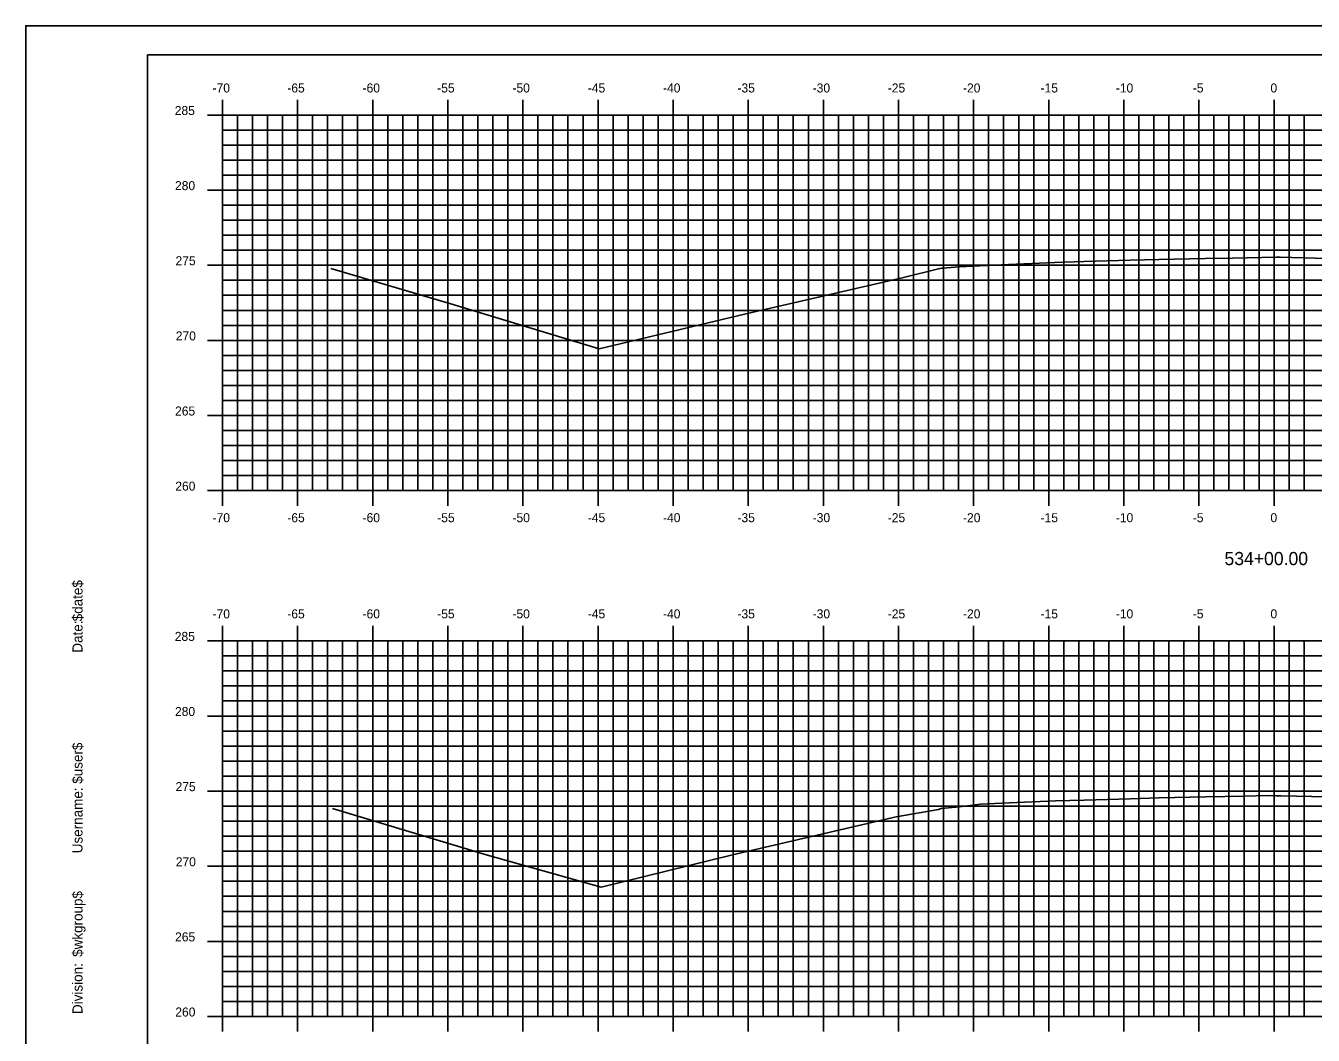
# Model space of a CAD drawing. Extents: x 1168600 to 1177589, y 610178 to 611246.
# Drawn here: x 1176974.3 to 1177060, y 610311.6 to 610378.7 of the extents above; entities that cross this region are included whole.
import ezdxf

# ---------------------------------------------------------------- set-up
doc = ezdxf.new("R2010")
doc.units = 0
for name, color, linetype in [('_Construction', 7, 'Continuous'), ('_Station Equation', 7, 'Continuous'), ('H_V ANNOTATION', 7, 'Continuous'), ('MAJOR', 7, 'Continuous'), ('MINOR', 7, 'Continuous')]:
    doc.layers.add(name, color=color, linetype=linetype)

msp = doc.modelspace()

# ---------------------------------------------------------------- linework, layer by layer
at = {"layer": '_Construction'}
for p, q in [((1177142.411, 610376.801), (1176982.411, 610376.801)), ((1176982.411, 610376.801), (1176982.411, 610271.801))]:
    msp.add_line(p, q, dxfattribs=at)
msp.add_lwpolyline([(1176974.318, 610268.742), (1177144.318, 610268.742), (1177144.318, 610378.742), (1176974.318, 610378.742)], close=True, dxfattribs=at)
at = {"layer": '_Station Equation'}
for points in [[(1176994.615, 610362.588), (1177002.605, 610360.242), (1177012.495, 610357.244), (1177022.164, 610359.54), (1177032.652, 610361.968), (1177035.16, 610362.578), (1177035.167, 610362.579), (1177035.338, 610362.615), (1177036.481, 610362.688), (1177037.824, 610362.767), (1177039.741, 610362.851), (1177042.824, 610362.985), (1177044.74, 610363.042), (1177047.824, 610363.13), (1177049.739, 610363.175), (1177052.824, 610363.249), (1177054.635, 610363.282), (1177057.569, 610363.335), (1177057.67, 610363.334), (1177057.824, 610363.333), (1177060.917, 610363.258)], [(1176994.739, 610326.65), (1177004.903, 610323.576), (1177012.616, 610321.408), (1177021.362, 610323.562), (1177032.259, 610326.084), (1177035.076, 610326.571), (1177035.254, 610326.649), (1177036.481, 610326.762), (1177037.863, 610326.942), (1177039.773, 610327.021), (1177042.863, 610327.151), (1177044.772, 610327.208), (1177047.863, 610327.299), (1177049.771, 610327.347), (1177052.863, 610327.424), (1177055.432, 610327.474), (1177057.021, 610327.504), (1177057.547, 610327.496), (1177057.863, 610327.493), (1177060.963, 610327.422)]]:
    msp.add_lwpolyline(points, dxfattribs=at)
at = {"layer": 'MAJOR'}
for p, q in [((1176987.411, 610373.803), (1176987.411, 610372.801)), ((1176992.411, 610373.803), (1176992.411, 610372.801)), ((1176997.411, 610373.803), (1176997.411, 610372.801)), ((1177002.411, 610373.803), (1177002.411, 610372.801)), ((1177007.411, 610373.803), (1177007.411, 610372.801)), ((1177012.411, 610373.803), (1177012.411, 610372.801)), ((1177017.411, 610373.803), (1177017.411, 610372.801)), ((1177022.411, 610373.803), (1177022.411, 610372.801)), ((1177027.411, 610373.803), (1177027.411, 610372.801)), ((1177032.411, 610373.803), (1177032.411, 610372.801)), ((1177037.411, 610373.803), (1177037.411, 610372.801)), ((1177042.411, 610373.803), (1177042.411, 610372.801)), ((1177047.411, 610373.803), (1177047.411, 610372.801)), ((1177052.411, 610373.803), (1177052.411, 610372.801)), ((1177057.411, 610373.803), (1177057.411, 610372.801)), ((1176986.409, 610372.801), (1176987.411, 610372.801)), ((1176987.411, 610372.801), (1177127.411, 610372.801)), ((1176987.411, 610347.801), (1176987.411, 610372.801)), ((1176987.411, 610347.801), (1176987.411, 610372.801)), ((1176987.411, 610372.801), (1177127.411, 610372.801)), ((1176992.411, 610347.801), (1176992.411, 610372.801)), ((1176997.411, 610347.801), (1176997.411, 610372.801)), ((1177002.411, 610347.801), (1177002.411, 610372.801)), ((1177007.411, 610347.801), (1177007.411, 610372.801)), ((1177012.411, 610347.801), (1177012.411, 610372.801)), ((1177017.411, 610347.801), (1177017.411, 610372.801)), ((1177022.411, 610347.801), (1177022.411, 610372.801)), ((1177027.411, 610347.801), (1177027.411, 610372.801)), ((1177032.411, 610347.801), (1177032.411, 610372.801)), ((1177037.411, 610347.801), (1177037.411, 610372.801)), ((1177042.411, 610347.801), (1177042.411, 610372.801)), ((1177047.411, 610347.801), (1177047.411, 610372.801)), ((1177052.411, 610347.801), (1177052.411, 610372.801)), ((1177057.411, 610347.801), (1177057.411, 610372.801)), ((1176986.409, 610367.801), (1176987.411, 610367.801)), ((1176987.411, 610367.801), (1177127.411, 610367.801)), ((1176986.409, 610362.801), (1176987.411, 610362.801)), ((1176987.411, 610362.801), (1177127.411, 610362.801)), ((1176986.409, 610357.801), (1176987.411, 610357.801)), ((1176987.411, 610357.801), (1177127.411, 610357.801)), ((1176986.409, 610352.801), (1176987.411, 610352.801)), ((1176987.411, 610352.801), (1177127.411, 610352.801)), ((1176986.409, 610347.801), (1176987.411, 610347.801)), ((1176987.411, 610347.801), (1177127.411, 610347.801)), ((1176987.411, 610347.801), (1177127.411, 610347.801)), ((1176987.411, 610346.799), (1176987.411, 610347.801)), ((1176992.411, 610346.799), (1176992.411, 610347.801)), ((1176997.411, 610346.799), (1176997.411, 610347.801)), ((1177002.411, 610346.799), (1177002.411, 610347.801)), ((1177007.411, 610346.799), (1177007.411, 610347.801)), ((1177012.411, 610346.799), (1177012.411, 610347.801)), ((1177017.411, 610346.799), (1177017.411, 610347.801)), ((1177022.411, 610346.799), (1177022.411, 610347.801)), ((1177027.411, 610346.799), (1177027.411, 610347.801)), ((1177032.411, 610346.799), (1177032.411, 610347.801)), ((1177037.411, 610346.799), (1177037.411, 610347.801)), ((1177042.411, 610346.799), (1177042.411, 610347.801)), ((1177047.411, 610346.799), (1177047.411, 610347.801)), ((1177052.411, 610346.799), (1177052.411, 610347.801)), ((1177057.411, 610346.799), (1177057.411, 610347.801)), ((1176987.411, 610338.803), (1176987.411, 610337.801)), ((1176992.411, 610338.803), (1176992.411, 610337.801)), ((1176997.411, 610338.803), (1176997.411, 610337.801)), ((1177002.411, 610338.803), (1177002.411, 610337.801)), ((1177007.411, 610338.803), (1177007.411, 610337.801)), ((1177012.411, 610338.803), (1177012.411, 610337.801)), ((1177017.411, 610338.803), (1177017.411, 610337.801)), ((1177022.411, 610338.803), (1177022.411, 610337.801)), ((1177027.411, 610338.803), (1177027.411, 610337.801)), ((1177032.411, 610338.803), (1177032.411, 610337.801)), ((1177037.411, 610338.803), (1177037.411, 610337.801)), ((1177042.411, 610338.803), (1177042.411, 610337.801)), ((1177047.411, 610338.803), (1177047.411, 610337.801)), ((1177052.411, 610338.803), (1177052.411, 610337.801)), ((1177057.411, 610338.803), (1177057.411, 610337.801)), ((1176986.409, 610337.801), (1176987.411, 610337.801)), ((1176987.411, 610337.801), (1177127.411, 610337.801)), ((1176987.411, 610312.801), (1176987.411, 610337.801)), ((1176987.411, 610312.801), (1176987.411, 610337.801)), ((1176987.411, 610337.801), (1177127.411, 610337.801)), ((1176992.411, 610312.801), (1176992.411, 610337.801)), ((1176997.411, 610312.801), (1176997.411, 610337.801)), ((1177002.411, 610312.801), (1177002.411, 610337.801)), ((1177007.411, 610312.801), (1177007.411, 610337.801)), ((1177012.411, 610312.801), (1177012.411, 610337.801)), ((1177017.411, 610312.801), (1177017.411, 610337.801)), ((1177022.411, 610312.801), (1177022.411, 610337.801)), ((1177027.411, 610312.801), (1177027.411, 610337.801)), ((1177032.411, 610312.801), (1177032.411, 610337.801)), ((1177037.411, 610312.801), (1177037.411, 610337.801)), ((1177042.411, 610312.801), (1177042.411, 610337.801)), ((1177047.411, 610312.801), (1177047.411, 610337.801)), ((1177052.411, 610312.801), (1177052.411, 610337.801)), ((1177057.411, 610312.801), (1177057.411, 610337.801)), ((1176986.409, 610332.801), (1176987.411, 610332.801)), ((1176987.411, 610332.801), (1177127.411, 610332.801)), ((1176986.409, 610327.801), (1176987.411, 610327.801)), ((1176987.411, 610327.801), (1177127.411, 610327.801)), ((1176986.409, 610322.801), (1176987.411, 610322.801)), ((1176987.411, 610322.801), (1177127.411, 610322.801)), ((1176986.409, 610317.801), (1176987.411, 610317.801)), ((1176987.411, 610317.801), (1177127.411, 610317.801)), ((1176986.409, 610312.801), (1176987.411, 610312.801)), ((1176987.411, 610312.801), (1177127.411, 610312.801)), ((1176987.411, 610312.801), (1177127.411, 610312.801)), ((1176987.411, 610311.799), (1176987.411, 610312.801)), ((1176992.411, 610311.799), (1176992.411, 610312.801)), ((1176997.411, 610311.799), (1176997.411, 610312.801)), ((1177002.411, 610311.799), (1177002.411, 610312.801)), ((1177007.411, 610311.799), (1177007.411, 610312.801)), ((1177012.411, 610311.799), (1177012.411, 610312.801)), ((1177017.411, 610311.799), (1177017.411, 610312.801)), ((1177022.411, 610311.799), (1177022.411, 610312.801)), ((1177027.411, 610311.799), (1177027.411, 610312.801)), ((1177032.411, 610311.799), (1177032.411, 610312.801)), ((1177037.411, 610311.799), (1177037.411, 610312.801)), ((1177042.411, 610311.799), (1177042.411, 610312.801)), ((1177047.411, 610311.799), (1177047.411, 610312.801)), ((1177052.411, 610311.799), (1177052.411, 610312.801)), ((1177057.411, 610311.799), (1177057.411, 610312.801))]:
    msp.add_line(p, q, dxfattribs=at)
at = {"layer": 'MINOR'}
for p, q in [((1176988.411, 610347.801), (1176988.411, 610372.801)), ((1176989.411, 610347.801), (1176989.411, 610372.801)), ((1176990.411, 610347.801), (1176990.411, 610372.801)), ((1176991.411, 610347.801), (1176991.411, 610372.801)), ((1176993.411, 610347.801), (1176993.411, 610372.801)), ((1176994.411, 610347.801), (1176994.411, 610372.801)), ((1176995.411, 610347.801), (1176995.411, 610372.801)), ((1176996.411, 610347.801), (1176996.411, 610372.801)), ((1176998.411, 610347.801), (1176998.411, 610372.801)), ((1176999.411, 610347.801), (1176999.411, 610372.801)), ((1177000.411, 610347.801), (1177000.411, 610372.801)), ((1177001.411, 610347.801), (1177001.411, 610372.801)), ((1177003.411, 610347.801), (1177003.411, 610372.801)), ((1177004.411, 610347.801), (1177004.411, 610372.801)), ((1177005.411, 610347.801), (1177005.411, 610372.801)), ((1177006.411, 610347.801), (1177006.411, 610372.801)), ((1177008.411, 610347.801), (1177008.411, 610372.801)), ((1177009.411, 610347.801), (1177009.411, 610372.801)), ((1177010.411, 610347.801), (1177010.411, 610372.801)), ((1177011.411, 610347.801), (1177011.411, 610372.801)), ((1177013.411, 610347.801), (1177013.411, 610372.801)), ((1177014.411, 610347.801), (1177014.411, 610372.801)), ((1177015.411, 610347.801), (1177015.411, 610372.801)), ((1177016.411, 610347.801), (1177016.411, 610372.801)), ((1177018.411, 610347.801), (1177018.411, 610372.801)), ((1177019.411, 610347.801), (1177019.411, 610372.801)), ((1177020.411, 610347.801), (1177020.411, 610372.801)), ((1177021.411, 610347.801), (1177021.411, 610372.801)), ((1177023.411, 610347.801), (1177023.411, 610372.801)), ((1177024.411, 610347.801), (1177024.411, 610372.801)), ((1177025.411, 610347.801), (1177025.411, 610372.801)), ((1177026.411, 610347.801), (1177026.411, 610372.801)), ((1177028.411, 610347.801), (1177028.411, 610372.801)), ((1177029.411, 610347.801), (1177029.411, 610372.801)), ((1177030.411, 610347.801), (1177030.411, 610372.801)), ((1177031.411, 610347.801), (1177031.411, 610372.801)), ((1177033.411, 610347.801), (1177033.411, 610372.801)), ((1177034.411, 610347.801), (1177034.411, 610372.801)), ((1177035.411, 610347.801), (1177035.411, 610372.801)), ((1177036.411, 610347.801), (1177036.411, 610372.801)), ((1177038.411, 610347.801), (1177038.411, 610372.801)), ((1177039.411, 610347.801), (1177039.411, 610372.801)), ((1177040.411, 610347.801), (1177040.411, 610372.801)), ((1177041.411, 610347.801), (1177041.411, 610372.801)), ((1177043.411, 610347.801), (1177043.411, 610372.801)), ((1177044.411, 610347.801), (1177044.411, 610372.801)), ((1177045.411, 610347.801), (1177045.411, 610372.801)), ((1177046.411, 610347.801), (1177046.411, 610372.801)), ((1177048.411, 610347.801), (1177048.411, 610372.801)), ((1177049.411, 610347.801), (1177049.411, 610372.801)), ((1177050.411, 610347.801), (1177050.411, 610372.801)), ((1177051.411, 610347.801), (1177051.411, 610372.801)), ((1177053.411, 610347.801), (1177053.411, 610372.801)), ((1177054.411, 610347.801), (1177054.411, 610372.801)), ((1177055.411, 610347.801), (1177055.411, 610372.801)), ((1177056.411, 610347.801), (1177056.411, 610372.801)), ((1177058.411, 610347.801), (1177058.411, 610372.801)), ((1177059.411, 610347.801), (1177059.411, 610372.801)), ((1176987.411, 610371.801), (1177127.411, 610371.801)), ((1176987.411, 610371.801), (1176988.413, 610371.801)), ((1176987.411, 610370.801), (1177127.411, 610370.801)), ((1176987.411, 610370.801), (1176988.413, 610370.801)), ((1176987.411, 610369.801), (1177127.411, 610369.801)), ((1176987.411, 610369.801), (1176988.413, 610369.801)), ((1176987.411, 610368.801), (1177127.411, 610368.801)), ((1176987.411, 610368.801), (1176988.413, 610368.801)), ((1176987.411, 610366.801), (1177127.411, 610366.801)), ((1176987.411, 610366.801), (1176988.413, 610366.801)), ((1176987.411, 610365.801), (1177127.411, 610365.801)), ((1176987.411, 610365.801), (1176988.413, 610365.801)), ((1176987.411, 610364.801), (1177127.411, 610364.801)), ((1176987.411, 610364.801), (1176988.413, 610364.801)), ((1176987.411, 610363.801), (1177127.411, 610363.801)), ((1176987.411, 610363.801), (1176988.413, 610363.801)), ((1176987.411, 610361.801), (1177127.411, 610361.801)), ((1176987.411, 610361.801), (1176988.413, 610361.801)), ((1176987.411, 610360.801), (1177127.411, 610360.801)), ((1176987.411, 610360.801), (1176988.413, 610360.801)), ((1176987.411, 610359.801), (1177127.411, 610359.801)), ((1176987.411, 610359.801), (1176988.413, 610359.801)), ((1176987.411, 610358.801), (1177127.411, 610358.801)), ((1176987.411, 610358.801), (1176988.413, 610358.801)), ((1176987.411, 610356.801), (1177127.411, 610356.801)), ((1176987.411, 610356.801), (1176988.413, 610356.801)), ((1176987.411, 610355.801), (1177127.411, 610355.801)), ((1176987.411, 610355.801), (1176988.413, 610355.801)), ((1176987.411, 610354.801), (1177127.411, 610354.801)), ((1176987.411, 610354.801), (1176988.413, 610354.801)), ((1176987.411, 610353.801), (1177127.411, 610353.801)), ((1176987.411, 610353.801), (1176988.413, 610353.801)), ((1176987.411, 610351.801), (1177127.411, 610351.801)), ((1176987.411, 610351.801), (1176988.413, 610351.801)), ((1176987.411, 610350.801), (1177127.411, 610350.801)), ((1176987.411, 610350.801), (1176988.413, 610350.801)), ((1176987.411, 610349.801), (1177127.411, 610349.801)), ((1176987.411, 610349.801), (1176988.413, 610349.801)), ((1176987.411, 610348.801), (1177127.411, 610348.801)), ((1176987.411, 610348.801), (1176988.413, 610348.801)), ((1176988.411, 610312.801), (1176988.411, 610337.801)), ((1176989.411, 610312.801), (1176989.411, 610337.801)), ((1176990.411, 610312.801), (1176990.411, 610337.801)), ((1176991.411, 610312.801), (1176991.411, 610337.801)), ((1176993.411, 610312.801), (1176993.411, 610337.801)), ((1176994.411, 610312.801), (1176994.411, 610337.801)), ((1176995.411, 610312.801), (1176995.411, 610337.801)), ((1176996.411, 610312.801), (1176996.411, 610337.801)), ((1176998.411, 610312.801), (1176998.411, 610337.801)), ((1176999.411, 610312.801), (1176999.411, 610337.801)), ((1177000.411, 610312.801), (1177000.411, 610337.801)), ((1177001.411, 610312.801), (1177001.411, 610337.801)), ((1177003.411, 610312.801), (1177003.411, 610337.801)), ((1177004.411, 610312.801), (1177004.411, 610337.801)), ((1177005.411, 610312.801), (1177005.411, 610337.801)), ((1177006.411, 610312.801), (1177006.411, 610337.801)), ((1177008.411, 610312.801), (1177008.411, 610337.801)), ((1177009.411, 610312.801), (1177009.411, 610337.801)), ((1177010.411, 610312.801), (1177010.411, 610337.801)), ((1177011.411, 610312.801), (1177011.411, 610337.801)), ((1177013.411, 610312.801), (1177013.411, 610337.801)), ((1177014.411, 610312.801), (1177014.411, 610337.801)), ((1177015.411, 610312.801), (1177015.411, 610337.801)), ((1177016.411, 610312.801), (1177016.411, 610337.801)), ((1177018.411, 610312.801), (1177018.411, 610337.801)), ((1177019.411, 610312.801), (1177019.411, 610337.801)), ((1177020.411, 610312.801), (1177020.411, 610337.801)), ((1177021.411, 610312.801), (1177021.411, 610337.801)), ((1177023.411, 610312.801), (1177023.411, 610337.801)), ((1177024.411, 610312.801), (1177024.411, 610337.801)), ((1177025.411, 610312.801), (1177025.411, 610337.801)), ((1177026.411, 610312.801), (1177026.411, 610337.801)), ((1177028.411, 610312.801), (1177028.411, 610337.801)), ((1177029.411, 610312.801), (1177029.411, 610337.801)), ((1177030.411, 610312.801), (1177030.411, 610337.801)), ((1177031.411, 610312.801), (1177031.411, 610337.801)), ((1177033.411, 610312.801), (1177033.411, 610337.801)), ((1177034.411, 610312.801), (1177034.411, 610337.801)), ((1177035.411, 610312.801), (1177035.411, 610337.801)), ((1177036.411, 610312.801), (1177036.411, 610337.801)), ((1177038.411, 610312.801), (1177038.411, 610337.801)), ((1177039.411, 610312.801), (1177039.411, 610337.801)), ((1177040.411, 610312.801), (1177040.411, 610337.801)), ((1177041.411, 610312.801), (1177041.411, 610337.801)), ((1177043.411, 610312.801), (1177043.411, 610337.801)), ((1177044.411, 610312.801), (1177044.411, 610337.801)), ((1177045.411, 610312.801), (1177045.411, 610337.801)), ((1177046.411, 610312.801), (1177046.411, 610337.801)), ((1177048.411, 610312.801), (1177048.411, 610337.801)), ((1177049.411, 610312.801), (1177049.411, 610337.801)), ((1177050.411, 610312.801), (1177050.411, 610337.801)), ((1177051.411, 610312.801), (1177051.411, 610337.801)), ((1177053.411, 610312.801), (1177053.411, 610337.801)), ((1177054.411, 610312.801), (1177054.411, 610337.801)), ((1177055.411, 610312.801), (1177055.411, 610337.801)), ((1177056.411, 610312.801), (1177056.411, 610337.801)), ((1177058.411, 610312.801), (1177058.411, 610337.801)), ((1177059.411, 610312.801), (1177059.411, 610337.801)), ((1176987.411, 610336.801), (1177127.411, 610336.801)), ((1176987.411, 610336.801), (1176988.413, 610336.801)), ((1176987.411, 610335.801), (1177127.411, 610335.801)), ((1176987.411, 610335.801), (1176988.413, 610335.801)), ((1176987.411, 610334.801), (1177127.411, 610334.801)), ((1176987.411, 610334.801), (1176988.413, 610334.801)), ((1176987.411, 610333.801), (1177127.411, 610333.801)), ((1176987.411, 610333.801), (1176988.413, 610333.801)), ((1176987.411, 610331.801), (1177127.411, 610331.801)), ((1176987.411, 610331.801), (1176988.413, 610331.801)), ((1176987.411, 610330.801), (1177127.411, 610330.801)), ((1176987.411, 610330.801), (1176988.413, 610330.801)), ((1176987.411, 610329.801), (1177127.411, 610329.801)), ((1176987.411, 610329.801), (1176988.413, 610329.801)), ((1176987.411, 610328.801), (1177127.411, 610328.801)), ((1176987.411, 610328.801), (1176988.413, 610328.801)), ((1176987.411, 610326.801), (1177127.411, 610326.801)), ((1176987.411, 610326.801), (1176988.413, 610326.801)), ((1176987.411, 610325.801), (1177127.411, 610325.801)), ((1176987.411, 610325.801), (1176988.413, 610325.801)), ((1176987.411, 610324.801), (1177127.411, 610324.801)), ((1176987.411, 610324.801), (1176988.413, 610324.801)), ((1176987.411, 610323.801), (1177127.411, 610323.801)), ((1176987.411, 610323.801), (1176988.413, 610323.801)), ((1176987.411, 610321.801), (1177127.411, 610321.801)), ((1176987.411, 610321.801), (1176988.413, 610321.801)), ((1176987.411, 610320.801), (1177127.411, 610320.801)), ((1176987.411, 610320.801), (1176988.413, 610320.801)), ((1176987.411, 610319.801), (1177127.411, 610319.801)), ((1176987.411, 610319.801), (1176988.413, 610319.801)), ((1176987.411, 610318.801), (1177127.411, 610318.801)), ((1176987.411, 610318.801), (1176988.413, 610318.801)), ((1176987.411, 610316.801), (1177127.411, 610316.801)), ((1176987.411, 610316.801), (1176988.413, 610316.801)), ((1176987.411, 610315.801), (1177127.411, 610315.801)), ((1176987.411, 610315.801), (1176988.413, 610315.801)), ((1176987.411, 610314.801), (1177127.411, 610314.801)), ((1176987.411, 610314.801), (1176988.413, 610314.801)), ((1176987.411, 610313.801), (1177127.411, 610313.801)), ((1176987.411, 610313.801), (1176988.413, 610313.801))]:
    msp.add_line(p, q, dxfattribs=at)

# ---------------------------------------------------------------- texts
at = {"layer": '_Construction'}
for s, p in [('$date$', (1176978.096, 610339.106)), ('Date:', (1176978.096, 610337.018)), ('$user$', (1176978.096, 610328.293)), ('Username:', (1176978.096, 610323.669)), ('$wkgroup$', (1176978.096, 610316.771)), ('Division:', (1176978.096, 610312.967))]:
    msp.add_text(s, height=0.6696, rotation=90, dxfattribs=at).set_placement(p)
at = {"layer": 'H_V ANNOTATION'}
for s, height, p in [('-70', 0.6, (1176986.753, 610374.301)), ('-65', 0.6, (1176991.729, 610374.301)), ('-60', 0.6, (1176996.737, 610374.301)), ('-55', 0.6, (1177001.707, 610374.301)), ('-50', 0.6, (1177006.715, 610374.301)), ('-45', 0.6, (1177011.729, 610374.301)), ('-40', 0.6, (1177016.737, 610374.301)), ('-35', 0.6, (1177021.691, 610374.301)), ('-30', 0.6, (1177026.699, 610374.301)), ('-25', 0.6, (1177031.697, 610374.301)), ('-20', 0.6, (1177036.705, 610374.301)), ('-15', 0.6, (1177041.868, 610374.301)), ('-10', 0.6, (1177046.876, 610374.301)), ('-5', 0.6, (1177052.002, 610374.301)), ('0', 0.6, (1177057.17, 610374.301)), ('285', 0.6, (1176984.236, 610372.801)), ('280', 0.6, (1176984.252, 610367.801)), ('275', 0.6, (1176984.289, 610362.801)), ('270', 0.6, (1176984.305, 610357.801)), ('265', 0.6, (1176984.257, 610352.801)), ('260', 0.6, (1176984.273, 610347.801)), ('-70', 0.6, (1176986.753, 610345.701)), ('-65', 0.6, (1176991.729, 610345.701)), ('-60', 0.6, (1176996.737, 610345.701)), ('-55', 0.6, (1177001.707, 610345.701)), ('-50', 0.6, (1177006.715, 610345.701)), ('-45', 0.6, (1177011.729, 610345.701)), ('-40', 0.6, (1177016.737, 610345.701)), ('-35', 0.6, (1177021.691, 610345.701)), ('-30', 0.6, (1177026.699, 610345.701)), ('-25', 0.6, (1177031.697, 610345.701)), ('-20', 0.6, (1177036.705, 610345.701)), ('-15', 0.6, (1177041.868, 610345.701)), ('-10', 0.6, (1177046.876, 610345.701)), ('-5', 0.6, (1177052.002, 610345.701)), ('0', 0.6, (1177057.17, 610345.701)), ('534+00.00', 0.875, (1177054.11, 610342.844)), ('-70', 0.6, (1176986.753, 610339.301)), ('-65', 0.6, (1176991.729, 610339.301)), ('-60', 0.6, (1176996.737, 610339.301)), ('-55', 0.6, (1177001.707, 610339.301)), ('-50', 0.6, (1177006.715, 610339.301)), ('-45', 0.6, (1177011.729, 610339.301)), ('-40', 0.6, (1177016.737, 610339.301)), ('-35', 0.6, (1177021.691, 610339.301)), ('-30', 0.6, (1177026.699, 610339.301)), ('-25', 0.6, (1177031.697, 610339.301)), ('-20', 0.6, (1177036.705, 610339.301)), ('-15', 0.6, (1177041.868, 610339.301)), ('-10', 0.6, (1177046.876, 610339.301)), ('-5', 0.6, (1177052.002, 610339.301)), ('0', 0.6, (1177057.17, 610339.301)), ('285', 0.6, (1176984.236, 610337.801)), ('280', 0.6, (1176984.252, 610332.801)), ('275', 0.6, (1176984.289, 610327.801)), ('270', 0.6, (1176984.305, 610322.801)), ('265', 0.6, (1176984.257, 610317.801)), ('260', 0.6, (1176984.273, 610312.801))]:
    msp.add_text(s, height=height, dxfattribs=at).set_placement(p)

doc.saveas('drawing.dxf')
